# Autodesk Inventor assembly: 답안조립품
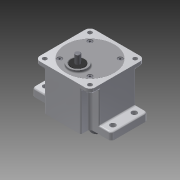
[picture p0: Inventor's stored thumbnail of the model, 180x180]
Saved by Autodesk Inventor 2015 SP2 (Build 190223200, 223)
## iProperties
Created: 2015-06
Part Number: 답안조립품
Document SubType Name: Assembly
Designer: AMC
Author: AMC
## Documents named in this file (12)
- C:\Users\AMC\Desktop\450620V1018\답안조립품.iam
- C:\Users\AMC\Desktop\450620V1018\본체.ipt
- C:\Users\AMC\Desktop\450620V1018\커버.ipt
- C:\Users\AMC\Desktop\450620V1018\베어링 608.ipt
- 베어링 608.ipt
- C:\Users\AMC\Desktop\450620V1018\베어링 6003.ipt
- 베어링 6003.ipt
- C:\Users\AMC\Desktop\450620V1018\오일실 17x32x8.ipt
- C:\Users\AMC\Desktop\450620V1018\오일실 8x22x7.ipt
- C:\Users\AMC\Desktop\450620V1018\서브축.ipt
- C:\Users\AMC\Desktop\450620V1018\메인축.ipt
- C:\Users\AMC\Desktop\450620V1018\M4x0.5x16.ipt
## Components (4 placed, 1 different names)
1. M4x0.5x12:1
2. M4x0.5x12:2
3. M4x0.5x12:3
4. M4x0.5x12:4
